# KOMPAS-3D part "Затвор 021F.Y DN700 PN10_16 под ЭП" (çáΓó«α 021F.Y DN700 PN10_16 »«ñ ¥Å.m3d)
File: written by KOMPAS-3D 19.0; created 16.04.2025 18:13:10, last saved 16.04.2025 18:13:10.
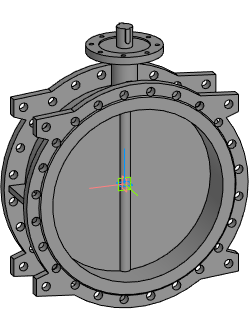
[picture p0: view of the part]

Document properties: Автор: Евгений; Полное имя файла: E:\Dendor Работа Сачек\3D для проекитирвщиков\1.6 Тип 021F.Y Затвор дисковый поворотный фланцевый\stp_Тип 021F.Y Затвор  DN40 PN10_16 под ЭП\Затвор 021F.Y DN700 PN10_16 под ЭП.m3d

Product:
- Part/product: Затвор 021F.Y DN700 PN10_16 под ЭП

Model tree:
1. Операция без истории:1  (labels: Затвор 021F.Y DN700 PN10_16 под ЭП)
